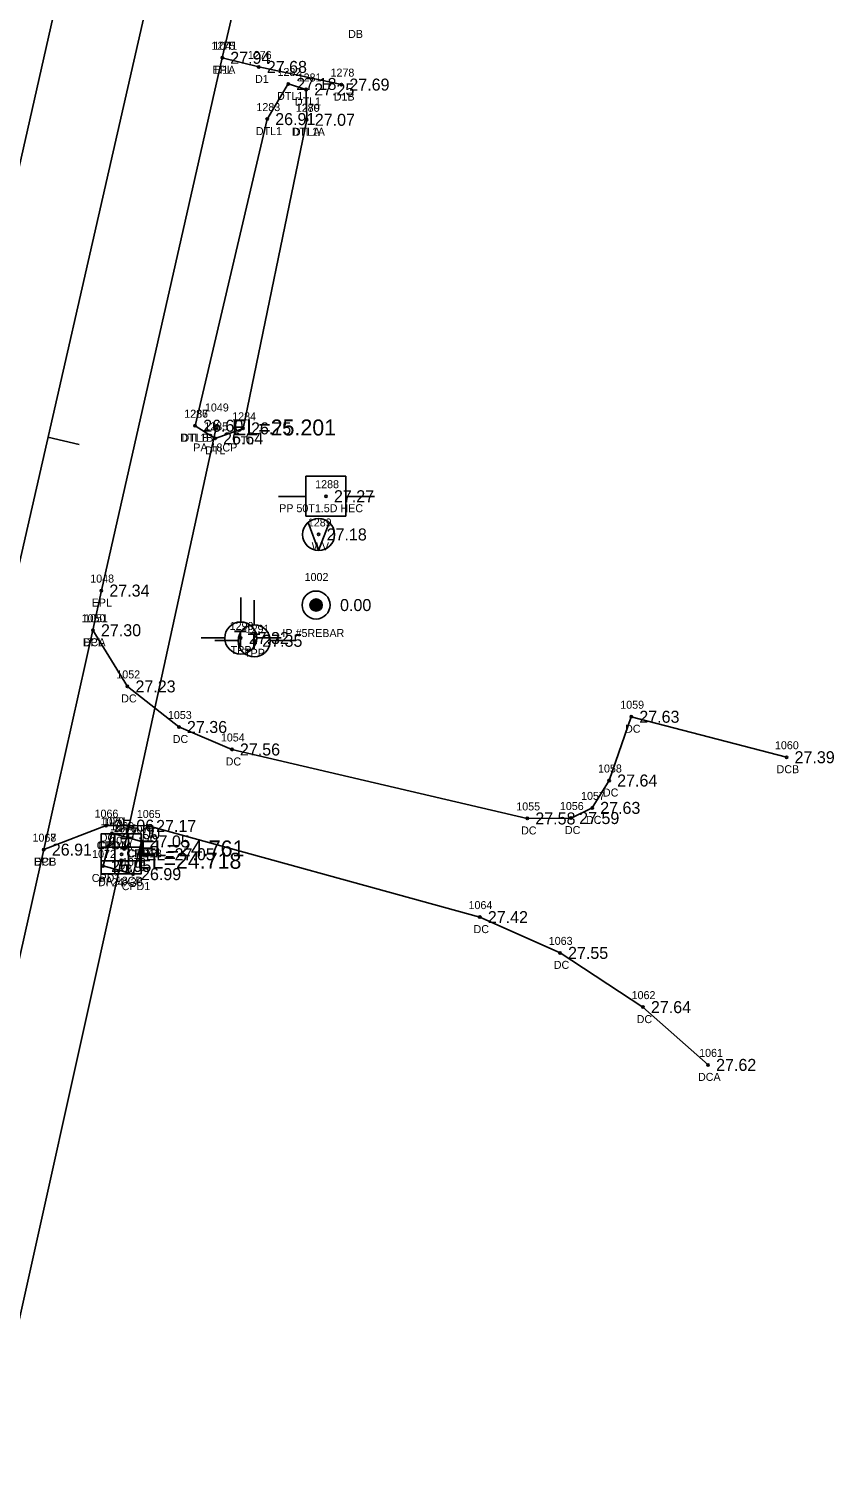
# Model space of a CAD drawing. Extents: x 2654414 to 2656963, y 761776 to 764965.
# Drawn here: x 2656009.2 to 2656109.9, y 764411.4 to 764592.8 of the extents above; entities that cross this region are included whole.
import ezdxf

# ---------------------------------------------------------------- set-up
doc = ezdxf.new("R2010")
doc.units = 0
for name, color, linetype in [('Default', 7, 'Continuous'), ('RD_EX_Conc', 7, 'Continuous'), ('RD_EX_Conc_txCode', 7, 'Continuous'), ('RD_EX_DR_Inlet', 7, 'Continuous'), ('RD_EX_DR_Inlet_txCode', 7, 'Continuous'), ('RD_EX_DR_Pipe', 7, 'Continuous'), ('RD_EX_DR_Pipe_txCode', 7, 'Continuous'), ('RD_EX_Driveway', 7, 'Continuous'), ('RD_EX_Driveway_txCode', 7, 'Continuous'), ('RD_EX_DV_Prop_txCode', 7, 'Continuous'), ('RD_EX_DV_PropPin', 7, 'Continuous'), ('RD_EX_H2O', 7, 'Continuous'), ('RD_EX_H2O_txCode', 7, 'Continuous'), ('RD_EX_Road', 7, 'Continuous'), ('RD_EX_Road_txCode', 7, 'Continuous'), ('RD_EX_TX_Conc_ELEV', 7, 'Continuous'), ('RD_EX_TX_DR_Inlet_ELEV', 7, 'Continuous'), ('RD_EX_TX_Driveway_ELEV', 7, 'Continuous'), ('RD_EX_TX_DV_Prop_ELEV', 7, 'Continuous'), ('RD_EX_TX_H2O_ELEV', 7, 'Continuous'), ('RD_EX_TX_Road_ELEV', 7, 'Continuous'), ('RD_EX_TX_UT_ELEV', 7, 'Continuous'), ('RD_EX_UT', 7, 'Continuous'), ('RD_EX_UT_txCode', 7, 'Continuous'), ('RD_HC_Cl', 7, 'Continuous'), ('RD_HC_Data_Tic', 7, 'Continuous'), ('RD_HC_Survey_ELEV', 7, 'Continuous'), ('RD_SMD_Locator', 7, 'Continuous'), ('RD_TX_Pipe_ElevEX', 7, 'Continuous')]:
    doc.layers.add(name, color=color, linetype=linetype)

msp = doc.modelspace()

# ---------------------------------------------------------------- linework, layer by layer
at = {"layer": 'Default'}
msp.add_line((2656050.51, 764712.37), (2655383.26, 761787.51), dxfattribs=at)
at = {"layer": 'RD_EX_Conc'}
msp.add_line((2656019.59, 764492.26), (2656023.3, 764491.25), dxfattribs=at)
for points in [[(2656017.22, 764517.64), (2656021.53, 764510.62), (2656027.97, 764505.55), (2656034.59, 764502.74), (2656071.52, 764494.12), (2656077, 764494.17), (2656079.63, 764495.44), (2656081.75, 764498.86), (2656084.52, 764506.83), (2656103.93, 764501.77)], [(2656094.12, 764463.32), (2656085.97, 764470.54), (2656075.61, 764477.32), (2656065.58, 764481.79), (2656024.11, 764493.18), (2656018.85, 764493.22), (2656011.07, 764490.22)], [(2656019.59, 764492.26), (2656018.49, 764488.18), (2656022.23, 764487.16), (2656023.3, 764491.25)]]:
    msp.add_lwpolyline(points, dxfattribs=at)
at = {"layer": 'RD_EX_DR_Inlet'}
for p, q in [((2656019.96, 764492.21), (2656019.96, 764487.21)), ((2656021.66, 764492.21), (2656021.66, 764487.21)), ((2656018.26, 764490.51), (2656023.26, 764490.51)), ((2656018.26, 764488.81), (2656023.26, 764488.81))]:
    msp.add_line(p, q, dxfattribs=at)
msp.add_lwpolyline([(2656018.26, 764487.21), (2656018.26, 764492.21), (2656023.26, 764492.21), (2656023.26, 764487.21)], close=True, dxfattribs=at)
at = {"layer": 'RD_EX_DR_Pipe'}
for p, q in [((2656032.6, 764542.98), (2656021.14, 764490.37)), ((2656020.76, 764488.83), (2656001.47, 764402.19))]:
    msp.add_line(p, q, dxfattribs=at)
at = {"layer": 'RD_EX_Driveway'}
msp.add_lwpolyline([(2656033.38, 764589.18), (2656037.95, 764588.04), (2656048.27, 764585.83)], dxfattribs=at)
at = {"layer": 'RD_EX_DV_PropPin'}
for p, q in [((2656044.44, 764520.42), (2656044.44, 764521.16)), ((2656044.48, 764520.36), (2656044.48, 764521.22)), ((2656044.51, 764520.31), (2656044.51, 764521.26)), ((2656044.55, 764520.27), (2656044.55, 764521.3)), ((2656044.58, 764520.24), (2656044.58, 764521.34)), ((2656044.62, 764520.21), (2656044.62, 764521.37)), ((2656044.65, 764520.18), (2656044.65, 764521.4)), ((2656044.69, 764520.15), (2656044.69, 764521.42)), ((2656044.72, 764520.13), (2656044.72, 764521.45)), ((2656044.76, 764520.11), (2656044.76, 764521.46)), ((2656044.79, 764520.1), (2656044.79, 764521.48)), ((2656044.83, 764520.08), (2656044.83, 764521.5)), ((2656044.86, 764520.07), (2656044.86, 764521.51)), ((2656044.9, 764520.06), (2656044.9, 764521.52)), ((2656044.93, 764520.05), (2656044.93, 764521.53)), ((2656044.97, 764520.04), (2656044.97, 764521.54)), ((2656045, 764520.04), (2656045, 764521.54)), ((2656045.04, 764520.03), (2656045.04, 764521.55)), ((2656045.07, 764520.03), (2656045.07, 764521.55)), ((2656045.11, 764520.03), (2656045.11, 764521.55)), ((2656045.14, 764520.03), (2656045.14, 764521.55)), ((2656045.18, 764520.03), (2656045.18, 764521.55)), ((2656045.21, 764520.04), (2656045.21, 764521.54)), ((2656045.25, 764520.04), (2656045.25, 764521.54)), ((2656045.28, 764520.05), (2656045.28, 764521.53)), ((2656045.32, 764520.06), (2656045.32, 764521.52)), ((2656045.35, 764520.07), (2656045.35, 764521.51)), ((2656045.39, 764520.08), (2656045.39, 764521.5)), ((2656045.42, 764520.1), (2656045.42, 764521.48)), ((2656045.46, 764520.11), (2656045.46, 764521.46)), ((2656045.49, 764520.13), (2656045.49, 764521.45)), ((2656045.53, 764520.15), (2656045.53, 764521.42)), ((2656045.56, 764520.18), (2656045.56, 764521.4)), ((2656045.6, 764520.21), (2656045.6, 764521.37)), ((2656045.63, 764520.24), (2656045.63, 764521.34)), ((2656045.67, 764520.27), (2656045.67, 764521.3)), ((2656045.7, 764520.31), (2656045.7, 764521.26)), ((2656045.74, 764520.36), (2656045.74, 764521.22)), ((2656045.77, 764520.42), (2656045.77, 764521.16)), ((2656044.37, 764520.59), (2656044.37, 764520.99)), ((2656044.41, 764520.49), (2656044.41, 764521.09)), ((2656045.81, 764520.49), (2656045.81, 764521.09)), ((2656045.84, 764520.59), (2656045.84, 764520.99))]:
    msp.add_line(p, q, dxfattribs=at)
for radius in [1.75, 0.761]:
    msp.add_circle((2656045.11, 764520.79), radius, dxfattribs=at)
at = {"layer": 'RD_EX_H2O'}
for points in [[(2656043.95, 764581.43), (2656043.87, 764585.22), (2656041.64, 764585.91), (2656039, 764581.52), (2656029.99, 764543.2)], [(2656043.95, 764581.43), (2656035.98, 764542.87), (2656032.48, 764541.62), (2656029.99, 764543.2)]]:
    msp.add_lwpolyline(points, dxfattribs=at)
at = {"layer": 'RD_EX_Road'}
for points in [[(2656041.72, 764723.31), (2656018.5, 764622.03), (2656002.75, 764552.49), (2655997.43, 764530.02), (2655974.74, 764429.64), (2655952.97, 764333.57), (2655930.52, 764235.7), (2655909.18, 764142.93), (2655887.93, 764050.57), (2655866.91, 763957.26), (2655846.82, 763869.53), (2655845.21, 763862.22), (2655839.99, 763839.71), (2655823.38, 763766.66), (2655801.33, 763669.93), (2655780.03, 763576.53), (2655774.26, 763551.85), (2655771.37, 763539.86), (2655759.09, 763486.9), (2655736.94, 763391.72), (2655715.19, 763296.77), (2655711.35, 763278.45)], [(2656062.87, 764717.57), (2656039.84, 764617.04), (2656035.41, 764597.94), (2656033.38, 764589.18), (2656018.27, 764522.6), (2656017.22, 764517.64), (2656011.07, 764490.22), (2655996.52, 764425.63), (2655974.03, 764327.02), (2655960.71, 764269.34), (2655951.96, 764231.59), (2655930.84, 764138.62), (2655926.81, 764121.01), (2655909.26, 764045.26), (2655908.15, 764039.87), (2655902.08, 764013.51), (2655888.19, 763952.26), (2655880.73, 763919.6), (2655875, 763893.73), (2655866.73, 763857), (2655852.89, 763796.34), (2655850.73, 763786.52)]]:
    msp.add_lwpolyline(points, dxfattribs=at)
at = {"layer": 'RD_EX_UT'}
for p, q in [((2656048.84, 764536.9), (2656043.84, 764536.9)), ((2656043.84, 764536.9), (2656043.84, 764531.9)), ((2656048.84, 764531.9), (2656048.84, 764536.9)), ((2656040.41, 764534.34), (2656043.88, 764534.34)), ((2656048.77, 764534.34), (2656052.41, 764534.34)), ((2656043.84, 764531.9), (2656048.84, 764531.9)), ((2656045.43, 764527.61), (2656044.12, 764531.1)), ((2656045.43, 764527.61), (2656046.75, 764531.06)), ((2656035.69, 764521.74), (2656035.69, 764518.67)), ((2656037.38, 764521.39), (2656037.38, 764518.32)), ((2656030.76, 764516.68), (2656033.69, 764516.68)), ((2656032.45, 764516.34), (2656035.38, 764516.34)), ((2656037.69, 764516.68), (2656040.76, 764516.68)), ((2656039.38, 764516.34), (2656042.45, 764516.34))]:
    msp.add_line(p, q, dxfattribs=at)
for centre in [(2656045.43, 764529.61), (2656035.69, 764516.67), (2656037.38, 764516.32)]:
    msp.add_circle(centre, 2, dxfattribs=at)
at = {"layer": 'RD_HC_Cl'}
msp.add_line((2656050.51, 764712.37), (2655383.26, 761787.51), dxfattribs=at)
at = {"layer": 'RD_HC_Data_Tic'}
msp.add_line((2656011.59, 764541.75), (2656015.49, 764540.86), dxfattribs=at)
at = {"layer": 'RD_SMD_Locator'}
for centre, radius in [((2656033.38, 764589.18), 0.15), ((2656033.38, 764589.18), 0.15), ((2656037.95, 764588.04), 0.15), ((2656041.64, 764585.91), 0.15), ((2656043.87, 764585.22), 0.15), ((2656048.27, 764585.83), 0.15), ((2656039, 764581.52), 0.15), ((2656043.95, 764581.43), 0.15), ((2656043.95, 764581.43), 0.15), ((2656029.99, 764543.2), 0.15), ((2656029.99, 764543.2), 0.15), ((2656032.6, 764542.98), 0.2), ((2656035.98, 764542.87), 0.15), ((2656032.48, 764541.62), 0.15), ((2656046.35, 764534.39), 0.15), ((2656045.43, 764529.61), 0.15), ((2656018.27, 764522.6), 0.15), ((2656045.11, 764520.79), 0.15), ((2656017.22, 764517.64), 0.15), ((2656017.22, 764517.64), 0.15), ((2656035.69, 764516.67), 0.15), ((2656037.38, 764516.32), 0.15), ((2656021.53, 764510.62), 0.15), ((2656084.52, 764506.83), 0.15), ((2656027.97, 764505.55), 0.15), ((2656034.59, 764502.74), 0.15), ((2656103.93, 764501.77), 0.15), ((2656081.75, 764498.86), 0.15), ((2656071.52, 764494.12), 0.15), ((2656077, 764494.17), 0.15), ((2656079.63, 764495.44), 0.15), ((2656018.85, 764493.22), 0.15), ((2656019.59, 764492.26), 0.15), ((2656019.59, 764492.26), 0.15), ((2656024.11, 764493.18), 0.15), ((2656011.07, 764490.22), 0.15), ((2656011.07, 764490.22), 0.15), ((2656021.14, 764490.37), 0.2), ((2656023.3, 764491.25), 0.15), ((2656023.3, 764491.25), 0.15), ((2656020.76, 764488.83), 0.2), ((2656020.8, 764489.65), 0.15), ((2656018.49, 764488.18), 0.15), ((2656022.23, 764487.16), 0.15), ((2656065.58, 764481.79), 0.15), ((2656075.61, 764477.32), 0.15), ((2656085.97, 764470.54), 0.15), ((2656094.12, 764463.32), 0.15)]:
    msp.add_circle(centre, radius, dxfattribs=at)

# ---------------------------------------------------------------- texts
at = {"layer": 'RD_EX_Conc_txCode'}
for s, p in [('1051', (2656016.12, 764518.64)), ('DCA', (2656015.96, 764515.64)), ('1052', (2656020.14, 764511.62)), ('DC', (2656020.75, 764508.62)), ('1059', (2656083.14, 764507.83)), ('1053', (2656026.59, 764506.55)), ('DC', (2656083.74, 764504.83)), ('DC', (2656027.19, 764503.55)), ('1054', (2656033.21, 764503.74)), ('1060', (2656102.48, 764502.77)), ('DC', (2656033.81, 764500.74)), ('1058', (2656080.36, 764499.86)), ('DCB', (2656102.68, 764499.77)), ('DC', (2656080.97, 764496.86)), ('1055', (2656070.14, 764495.12)), ('1056', (2656075.59, 764495.17)), ('1057', (2656078.24, 764496.44)), ('1066', (2656017.42, 764494.22)), ('1070', (2656018.16, 764493.26)), ('1071', (2656018.49, 764493.26)), ('1065', (2656022.7, 764494.18)), ('DC', (2656078.85, 764493.44)), ('1067', (2656009.66, 764491.22)), ('DC', (2656018.07, 764491.22)), ('1074', (2656021.92, 764492.25)), ('1075', (2656021.92, 764492.25)), ('DC', (2656023.33, 764491.18)), ('DC', (2656070.74, 764492.12)), ('DC', (2656076.22, 764492.17)), ('CPD1A', (2656017.68, 764490.26)), ('CPDA', (2656017.85, 764490.26)), ('DCB', (2656009.82, 764488.22)), ('1072', (2656017.11, 764489.18)), ('1073', (2656020.84, 764488.16)), ('CPD1B', (2656021.41, 764489.25)), ('CPDB', (2656021.58, 764489.25)), ('CPD1', (2656017.07, 764486.18)), ('CPD1', (2656020.81, 764485.16)), ('1064', (2656064.17, 764482.79)), ('DC', (2656064.8, 764479.79)), ('1063', (2656074.2, 764478.32)), ('DC', (2656074.83, 764475.32)), ('1062', (2656084.56, 764471.54)), ('DC', (2656085.19, 764468.54)), ('1061', (2656093, 764464.32)), ('DCA', (2656092.86, 764461.32))]:
    msp.add_text(s, height=1, dxfattribs=at).set_placement(p)
at = {"layer": 'RD_EX_DR_Inlet_txCode'}
for s, p in [('1069', (2656019.39, 764492.65)), ('DI 24X30', (2656017.85, 764485.65))]:
    msp.add_text(s, height=1, dxfattribs=at).set_placement(p)
at = {"layer": 'RD_EX_DR_Pipe_txCode'}
for s, p in [('1049', (2656031.22, 764544.98)), ('PA 18CP', (2656029.76, 764539.98)), ('1076', (2656019.73, 764492.37)), ('1077', (2656019.38, 764490.83)), ('PA 18CP', (2656017.92, 764485.83)), ('PB', (2656020.36, 764487.37))]:
    msp.add_text(s, height=1, dxfattribs=at).set_placement(p)
at = {"layer": 'RD_EX_Driveway_txCode'}
for s, p in [('DB', (2656049.12, 764591.66)), ('1275', (2656032.03, 764590.18)), ('1276', (2656036.58, 764589.04)), ('D1A', (2656032.42, 764587.18)), ('D1', (2656037.48, 764586.04)), ('1278', (2656046.92, 764586.83)), ('D1B', (2656047.32, 764583.83))]:
    msp.add_text(s, height=1, dxfattribs=at).set_placement(p)
at = {"layer": 'RD_EX_DV_Prop_txCode'}
for s, p in [('1002', (2656043.68, 764523.79)), ('IP #5REBAR', (2656040.91, 764516.79))]:
    msp.add_text(s, height=1, dxfattribs=at).set_placement(p)
at = {"layer": 'RD_EX_H2O_txCode'}
for s, p in [('1282', (2656040.29, 764586.91)), ('1281', (2656042.81, 764586.22)), ('DTL1', (2656040.23, 764583.91)), ('1283', (2656037.65, 764582.52)), ('DTL1', (2656042.46, 764583.22)), ('1280', (2656042.57, 764582.43)), ('1279', (2656042.61, 764582.43)), ('DTL1', (2656037.59, 764579.52)), ('DTL1A', (2656042.06, 764579.43)), ('DTLA', (2656042.22, 764579.43)), ('1286', (2656028.62, 764544.2)), ('1287', (2656028.65, 764544.2)), ('1284', (2656034.63, 764543.87)), ('1285', (2656031.13, 764542.62)), ('DTL1B', (2656028.11, 764541.2)), ('DTLB', (2656028.28, 764541.2)), ('DTL', (2656034.73, 764540.87)), ('DTL', (2656031.23, 764539.62))]:
    msp.add_text(s, height=1, dxfattribs=at).set_placement(p)
at = {"layer": 'RD_EX_Road_txCode'}
for s, p in [('1041', (2656032.27, 764590.18)), ('EPL', (2656032.17, 764587.18)), ('1048', (2656016.88, 764523.6)), ('EPL', (2656017.06, 764520.6)), ('1050', (2656015.8, 764518.64)), ('EPL', (2656016.02, 764515.64)), ('1068', (2656009.66, 764491.22)), ('EPL', (2656009.87, 764488.22))]:
    msp.add_text(s, height=1, dxfattribs=at).set_placement(p)
at = {"layer": 'RD_EX_TX_Conc_ELEV'}
for s, p in [('27.30', (2656018.22, 764516.89)), ('27.23', (2656022.53, 764509.87)), ('27.63', (2656085.52, 764506.08)), ('27.36', (2656028.97, 764504.8)), ('27.56', (2656035.59, 764501.99)), ('27.39', (2656104.93, 764501.02)), ('27.64', (2656082.75, 764498.11)), ('27.63', (2656080.63, 764494.69)), ('27.06', (2656019.85, 764492.47)), ('27.17', (2656025.11, 764492.43)), ('27.58', (2656072.52, 764493.37)), ('27.59', (2656078, 764493.42)), ('27.00', (2656020.59, 764491.51)), ('27.00', (2656020.59, 764491.51)), ('26.91', (2656012.07, 764489.47)), ('27.05', (2656024.3, 764490.5)), ('27.05', (2656024.3, 764490.5)), ('26.95', (2656019.49, 764487.43)), ('26.99', (2656023.23, 764486.41)), ('27.42', (2656066.58, 764481.04)), ('27.55', (2656076.61, 764476.57)), ('27.64', (2656086.97, 764469.79)), ('27.62', (2656095.12, 764462.57))]:
    msp.add_text(s, height=1.5, dxfattribs=at).set_placement(p)
at = {"layer": 'RD_EX_TX_DR_Inlet_ELEV'}
msp.add_text('EL=27.05', height=1.5, dxfattribs=at).set_placement((2656023.8, 764488.9))
at = {"layer": 'RD_EX_TX_Driveway_ELEV'}
for s, p in [('27.94', (2656034.38, 764588.43)), ('27.68', (2656038.95, 764587.29)), ('27.69', (2656049.27, 764585.08))]:
    msp.add_text(s, height=1.5, dxfattribs=at).set_placement(p)
at = {"layer": 'RD_EX_TX_DV_Prop_ELEV'}
msp.add_text('0.00', height=1.5, dxfattribs=at).set_placement((2656048.11, 764520.04))
at = {"layer": 'RD_EX_TX_H2O_ELEV'}
for s, p in [('27.18', (2656042.64, 764585.16)), ('27.25', (2656044.87, 764584.47)), ('26.91', (2656040, 764580.77)), ('27.07', (2656044.95, 764580.68)), ('27.07', (2656044.95, 764580.68)), ('26.60', (2656030.99, 764542.45)), ('26.60', (2656030.99, 764542.45)), ('26.75', (2656036.98, 764542.12)), ('26.64', (2656033.48, 764540.87))]:
    msp.add_text(s, height=1.5, dxfattribs=at).set_placement(p)
at = {"layer": 'RD_EX_TX_Road_ELEV'}
for s, p in [('27.94', (2656034.38, 764588.43)), ('27.34', (2656019.27, 764521.85)), ('27.30', (2656018.22, 764516.89)), ('26.91', (2656012.07, 764489.47))]:
    msp.add_text(s, height=1.5, dxfattribs=at).set_placement(p)
at = {"layer": 'RD_EX_TX_UT_ELEV'}
for s, p in [('27.18', (2656046.43, 764528.86)), ('27.32', (2656036.69, 764515.92)), ('27.35', (2656038.38, 764515.57))]:
    msp.add_text(s, height=1.5, dxfattribs=at).set_placement(p)
at = {"layer": 'RD_EX_UT'}
for p in [(2656034.84, 764515.62), (2656036.53, 764515.27)]:
    msp.add_text('T', height=2, dxfattribs=at).set_placement(p)
at = {"layer": 'RD_EX_UT_txCode'}
for s, p in [('1288', (2656045, 764535.39)), ('PP 50T1.5D HEC', (2656040.5, 764532.39)), ('1289', (2656044.08, 764530.61)), ('WV', (2656044.57, 764527.61)), ('1290', (2656034.31, 764517.67)), ('1291', (2656036.31, 764517.32)), ('TPP', (2656034.43, 764514.67)), ('TPP', (2656036.11, 764514.32))]:
    msp.add_text(s, height=1, dxfattribs=at).set_placement(p)
at = {"layer": 'RD_HC_Survey_ELEV'}
msp.add_text('27.27', height=1.5, dxfattribs=at).set_placement((2656047.35, 764533.64))
at = {"layer": 'RD_TX_Pipe_ElevEX'}
for s, p in [('EL=25.201', (2656034.6, 764541.98)), ('EL=24.761', (2656023.14, 764489.37)), ('EL=24.718', (2656022.76, 764487.83))]:
    msp.add_text(s, height=2, dxfattribs=at).set_placement(p)

doc.saveas('drawing.dxf')
